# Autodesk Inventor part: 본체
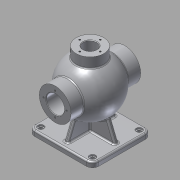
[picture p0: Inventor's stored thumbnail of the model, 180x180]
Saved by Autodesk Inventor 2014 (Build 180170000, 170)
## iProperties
Created: 2015-10
Part Number: 본체
Material: Aluminum 6061
Document SubType Name: Modeling
Designer: youjin14
Density: 2.71 g/cm^3
Appearance: Aluminum - Flat
Mass: 1509.57 g
Surface Area: 1153.7 cm^2
Volume: 557.037 cm^3
Author: youjin14
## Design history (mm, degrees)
sketch "Sketch1"
  geometry: L1 (-50.5, -57.5)-(50.5, -57.5); L2 (62.5, -45.5)-(62.5, 45.5); L3 (50.5, 57.5)-(-50.5, 57.5); L4 (-62.5, 45.5)-(-62.5, -45.5); L5 (-62.5, -57.5)-(62.5, 57.5); L6 (62.5, -57.5)-(-62.5, 57.5); A1 r 12 centre (-50.5, 45.5) between (-50.5, 57.5) and (-62.5, 45.5); A2 r 12 centre (-50.5, -45.5) between (-62.5, -45.5) and (-50.5, -57.5); A3 r 12 centre (50.5, -45.5) between (50.5, -57.5) and (62.5, -45.5); A4 r 12 centre (50.5, 45.5) between (62.5, 45.5) and (50.5, 57.5); 1 further point
  constraints: 12 end point, 8 point on circle, 8 point on line, 8 tangent, 4 centre point, 3 equal radius, 2 midpoint, 2 parallel, 1 horizontal, 1 perpendicular
  dimensions: "d0" = 125 distance of L6.end L5.end; "d1" = 115 distance of L5.end L6.start; "d2" = 12 radius of A1
extrude "Extrusion1" new body sketch "Sketch1" distance "d3" = 10; taper "d4" = 0 deg
sketch "Sketch2"
  geometry: A1 r 12 centre (-50.5, 45.5) between (-50.5, 57.5) and (-62.5, 45.5) reference; A2 r 12 centre (-50.5, -45.5) between (-62.5, -45.5) and (-50.5, -57.5) reference; A3 r 12 centre (50.5, -45.5) between (50.5, -57.5) and (62.5, -45.5) reference; A4 r 12 centre (50.5, 45.5) between (62.5, 45.5) and (50.5, 57.5) reference; 5 further points
  constraints: 4 coincident
  dimensions: "d5" = 101 distance of A4.centre A1.centre (derived); "d6" = 91 distance of A3.centre A4.centre (derived)
hole "Hole1" sketch "Sketch2" at (-50.5, 45.5), (50.5, 45.5), (-50.5, -45.5), (50.5, -45.5) diameter "d7" = 8; stored, may be unused: countersink angle "d11" = 90 deg, drill point angle "d13" = 0 deg; dims "d8" = 6, "d9" = 12, "d10" = 3, "d12" = 10
fillet "Fillet1" dims "d14" = 3
sketch "Sketch3"
  geometry: 2 further points
  constraints: 1 vertical alignment
  dimensions: "d15" = 85 distance of point (0, 0) point (0, 85)
sketch "Sketch4"
  geometry: L1 (36.862, 123.082)-(-36.862, 46.918); A1 r 53 centre (0, 85) between (36.862, 123.082) and (-36.862, 46.918); 1 further point
  constraints: 2 end point, 2 point on circle, 1 centre point, 1 midpoint
  dimensions: "d16" = 53 radius of A1
revolve "Revolution1" sketch "Sketch4" stored, may be unused: angle "d17" = 90 deg
sketch "Sketch5"
  geometry: L1 (-4, -4)-(4, -4); L2 (4, -4)-(4, 4); L3 (4, 4)-(-4, 4); L4 (-4, 4)-(-4, -4); L5 (-4, -4)-(4, 4); L6 (4, -4)-(-4, 4); 1 further point
  constraints: 12 end point, 2 midpoint, 2 parallel, 1 horizontal, 1 perpendicular
  dimensions: "d18" = 8 distance of L3.end L2.end; "d19" = 8 distance of L2.end L1.end
extrude "Extrusion2" join sketch "Sketch5" stored distance "d20" = 10; taper "d21" = 0 deg
sketch "Sketch6"
  geometry: L1 (-4, 10)-(-4, 32.303) reference; L2 (-50.5, 10)-(50.5, 10) reference; L3 (-56.5, 10)-(-44.5, 10) reference; L4 (44.5, 10)-(56.5, 10) reference; L5 (52.5, 10)-(37.379, 47.426); L6 (62.5, 0)-(62.5, 7) reference; L7 (-52.5, 10)-(-37.379, 47.426); L8 (-62.5, 0)-(-62.5, 7) reference; A1 r 53 centre (0, 85) between (4, 32.151) and (-4, 32.151) reference; 1 further point
  constraints: 4 end point, 2 point on circle, 2 point on line
  dimensions: "d22" = 10 distance from line of L6 L5.start; "d23" = 10 distance from line of L8 L7.start; "d24" = 22 deg angle of L7 L8; "d25" = 22 deg angle of L6 L5
feature "Rib1" dims "d26" = 1, "d27" = 8, "d28" = 0, "d29" = 0, "d30" = 1, "d31" = 1
feature "Rib2" dims "d32" = 1, "d33" = 8, "d34" = 0, "d35" = 0, "d36" = 1, "d37" = 1
sketch "Sketch7"
  geometry: L1 (-4, 10)-(-4, 47.578) reference; L2 (-45.5, 10)-(45.5, 10) reference; L3 (-51.5, 10)-(-39.5, 10) reference; L4 (39.5, 10)-(51.5, 10) reference; L5 (-54.5, 10)-(-45.5, 10) reference; L6 (45.5, 10)-(54.5, 10) reference; L7 (-47.5, 10)-(-33.719, 44.109); L8 (47.5, 10)-(33.719, 44.109); L9 (57.5, 0)-(57.5, 7) reference; L10 (-57.5, 0)-(-57.5, 7) reference; A1 r 53 centre (0, 85) between (4, 32.151) and (-4, 32.151) reference; 1 further point
  constraints: 4 end point, 2 point on circle, 2 point on line
  dimensions: "d38" = 10 distance from line of L9 L8.start; "d39" = 10 distance from line of L10 L7.start; "d40" = 22 deg angle of L10 L7; "d41" = 22 deg angle of L9 L8
feature "Rib3" dims "d42" = 1, "d43" = 8, "d44" = 0, "d45" = 0, "d46" = 1, "d47" = 1
feature "Rib4" dims "d48" = 1, "d49" = 8, "d50" = 0, "d51" = 0, "d52" = 1, "d53" = 1
sketch "Sketch8"
  geometry: C1 r 31 at (0, 85); 1 further point
  constraints: 1 centre point, 1 vertical alignment
  dimensions: "d54" = 62 diameter of C1; "d55" = 85 distance of point (0, 0) C1.centre
extrude "Extrusion3" join sketch "Sketch8" stored distance "d56" = 136; taper "d57" = 0 deg
sketch "Sketch9"
  geometry: L1 (42.475, 91.701)-(-42.475, 78.299); A1 r 43 centre (0, 85) between (42.475, 91.701) and (-42.475, 78.299); 1 further point
  constraints: 2 end point, 2 point on circle, 1 centre point, 1 midpoint
  dimensions: "d58" = 43 radius of A1
revolve "Revolution2" sketch "Sketch9" stored, may be unused: angle "d59" = 90 deg
sketch "Sketch10"
  geometry: C1 r 31 at (0, 0) reference; C2 r 17.5 at (0, 0); 1 further point
  constraints: 1 centre point, 1 coincident
  dimensions: "d60" = 35 diameter of C2
extrude "Extrusion4" cut sketch "Sketch10" stored distance "d61" = 136; taper "d62" = 0 deg
workplane "Work Plane1"
sketch "Sketch11"
  geometry: C1 r 27 at (0, 0); 1 further point
  constraints: 1 centre point, 1 coincident
  dimensions: "d64" = 54 diameter of C1
extrude "Extrusion5" join sketch "Sketch11" stored distance "d65" = 136; taper "d66" = 0 deg
sketch "Sketch12"
  geometry: C1 r 27 at (0, 0) reference; C2 r 13 at (0, 0)
  constraints: 1 centre point, 1 coincident
  dimensions: "d67" = 26 diameter of C2
extrude "Extrusion6" cut sketch "Sketch12" stored distance "d68" = 136; taper "d69" = 0 deg
workplane "Work Plane2"
sketch "Sketch13"
  geometry: L1 (45.5, -150)-(-45.5, -150) reference; L2 (-27, -19.393)-(27, -19.393) reference; L3 (-27, 0)-(27, 0) reference; 3 further points
  constraints: 1 midpoint, 1 vertical alignment, 1 other
  dimensions: "d70" = 10 distance from line of L3 point (0, -10)
emboss "Emboss1" sketch "Sketch13" dims "d0" = 125, "d1" = 115, "d2" = 12, "d71" = 0.5, "d72" = 0
sketch "Sketch14"
  geometry: C1 r 17.5 at (0, 0) reference; C2 r 31 at (0, 0) reference; A1 r 22.5 centre (0, 0) between (0, 22.5) and (-22.5, 0); 3 further points
  constraints: 4 point on circle, 2 horizontal alignment, 2 vertical alignment, 1 centre point, 1 coincident
  dimensions: "d73" = 45 diameter of A1
hole "Hole2" sketch "Sketch14" at (0, 22.5), (0, -22.5), (22.5, 0), (-22.5, 0) diameter "d74" = 3.242; stored, may be unused: countersink angle "d78" = 90 deg, drill point angle "d80" = 118 deg; dims "d75" = 12, "d76" = 12, "d77" = 3, "d79" = 15
sketch "Sketch15"
  geometry: C1 r 17.5 at (0, 0) reference; C2 r 31 at (0, 0) reference; A1 r 24 centre (0, 0) between (0, 24) and (-24, 0); 3 further points
  constraints: 4 point on circle, 2 horizontal alignment, 2 vertical alignment, 1 centre point, 1 coincident
  dimensions: "d81" = 48 diameter of A1
hole "Hole3" sketch "Sketch15" at (0, 24), (0, -24), (-24, 0), (24, 0) diameter "d82" = 3.242; stored, may be unused: countersink angle "d86" = 90 deg, drill point angle "d88" = 118 deg; dims "d83" = 16, "d84" = 12, "d85" = 3, "d87" = 19
sketch "Sketch16"
  geometry: C1 r 13 at (0, 0) reference; C2 r 27 at (0, 0) reference; A1 r 20 centre (0, 0) between (0, 20) and (-20, 0); 2 further points
  constraints: 4 point on circle, 2 horizontal alignment, 2 vertical alignment, 1 centre point, 1 coincident
  dimensions: "d89" = 40 diameter of A1
hole "Hole4" sketch "Sketch16" at (0, 20), (0, -20), (-20, 0), (20, 0) diameter "d90" = 3.242; stored, may be unused: countersink angle "d94" = 90 deg, drill point angle "d96" = 118 deg; dims "d91" = 9, "d92" = 12, "d93" = 3, "d95" = 11
workplane "Work Plane3"
sketch "Sketch17"
  geometry: C1 r 17.5 at (0, 85) reference; C2 r 18.5 at (0, 85); 1 further point
  constraints: 1 centre point, 1 coincident
  dimensions: "d98" = 37 diameter of C2
extrude "Extrusion7" cut sketch "Sketch17" distance "d99" = 1.75; taper "d100" = 0 deg
chamfer "Chamfer1" distance "d101" = 1; stored, may be unused: second distance "d102" = 2, angle "d103" = 45 deg
fillet "Fillet2" dims "d104" = 3
fillet "Fillet3" dims "d105" = 3
fillet "Fillet4" dims "d106" = 3
body "Solid1"
node "Projected Loop1"
other parameters: "d97" = -52
